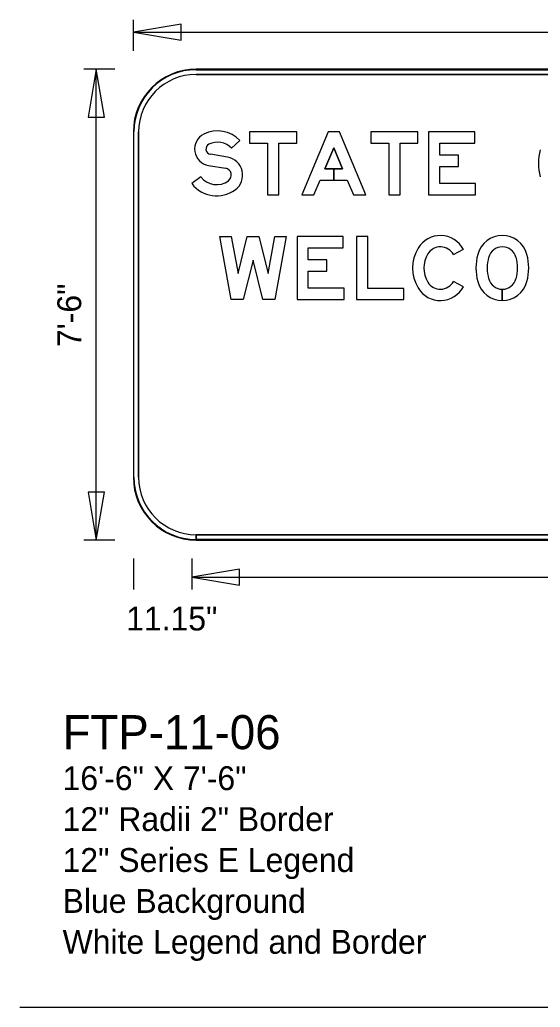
# Model space of a CAD drawing. Extents: x 0 to 770, y 0 to 495.
# Drawn here: x 0 to 76.3, y 330 to 474.8 of the extents above; entities that cross this region are included whole.
import ezdxf

# ---------------------------------------------------------------- set-up
doc = ezdxf.new("R2010")
doc.units = 0
for name, color, linetype in [('Default', 7, 'Continuous'), ('Dimension', 7, 'Continuous'), ('GSBWFill', 7, 'Continuous'), ('GSColorFill', 7, 'Continuous'), ('GSDims', 7, 'Continuous'), ('GSOutline', 7, 'Continuous'), ('SheetLines_dp', 7, 'Continuous')]:
    doc.layers.add(name, color=color, linetype=linetype)

msp = doc.modelspace()

# ---------------------------------------------------------------- linework, layer by layer
at = {"layer": 'Dimension'}
for points in [[(16.66, 473), (23.68, 471.81), (23.68, 474.19)], [(11.22, 467.56), (10.04, 460.55), (12.41, 460.55)], [(11.22, 398.51), (12.41, 405.53), (10.04, 405.53)], [(25.23, 393.07), (32.24, 391.88), (32.24, 394.26)]]:
    msp.add_lwpolyline(points, close=True, dxfattribs=at)
at = {"layer": 'GSBWFill'}
for p, q in [((159.37, 467.56), (25.87, 467.56)), ((159.37, 467.56), (25.87, 467.56)), ((25.87, 466.8), (159.37, 466.8)), ((16.66, 458.36), (16.66, 407.72)), ((16.66, 458.36), (16.66, 407.72)), ((17.43, 407.72), (17.43, 458.36)), ((31.05, 455.96), (32.27, 457.09)), ((30.46, 454.66), (27.95, 455.09)), ((27.67, 453.45), (30.18, 453.03)), ((26.54, 451.8), (25.23, 450.78)), ((63.58, 440.37), (65.05, 441.15)), ((65.05, 435.67), (63.58, 436.45)), ((63.58, 436.45), (63.58, 436.45)), ((70.75, 433.64), (70.75, 435.3)), ((70.75, 435.3), (70.75, 433.64)), ((25.87, 398.51), (25.87, 399.28)), ((25.87, 398.51), (159.37, 398.51)), ((159.37, 399.28), (25.88, 399.28)), ((25.88, 399.28), (25.88, 398.51)), ((25.88, 398.51), (159.37, 398.51))]:
    msp.add_line(p, q, dxfattribs=at)
for points in [[(33.7, 456.7), (36.32, 456.7), (36.32, 449.15), (37.98, 449.15), (37.98, 456.7), (40.6, 456.7), (40.6, 458.36), (33.7, 458.36)], [(47.33, 452.97), (46.03, 452.97), (46.03, 451.31), (48.02, 451.31), (48.93, 449.15), (50.73, 449.15), (46.86, 458.36), (45.2, 458.36), (41.34, 449.15), (43.14, 449.15), (44.04, 451.31), (46.03, 451.31), (46.03, 452.97), (44.74, 452.97), (46.03, 456.05)], [(51.47, 456.7), (54.09, 456.7), (54.09, 449.15), (55.75, 449.15), (55.75, 456.7), (58.37, 456.7), (58.37, 458.36), (51.47, 458.36)], [(66.84, 450.81), (61.59, 450.81), (61.59, 453.28), (64.31, 453.28), (64.31, 454.94), (61.59, 454.94), (61.59, 456.7), (66.7, 456.7), (66.7, 458.36), (59.94, 458.36), (59.94, 449.15), (66.84, 449.15)], [(34.2, 439.56), (32.75, 433.8), (31, 433.8), (29.32, 443.01), (31.01, 443.01), (32, 437.59), (33.36, 443.01), (35.04, 443.01), (36.41, 437.59), (37.4, 443.01), (39.08, 443.01), (37.4, 433.8), (35.65, 433.8)], [(47.55, 435.46), (42.3, 435.46), (42.3, 437.94), (45.02, 437.94), (45.02, 439.6), (42.3, 439.6), (42.3, 441.35), (47.41, 441.35), (47.41, 443.01), (40.65, 443.01), (40.65, 433.8), (47.55, 433.8)], [(56.3, 433.8), (56.3, 435.42), (51.05, 435.42), (51.05, 443.01), (49.39, 443.01), (49.39, 433.8)]]:
    msp.add_lwpolyline(points, close=True, dxfattribs=at)
for centre, radius, start, end in [((25.87, 458.36), 9.21, 90, 180), ((25.87, 458.36), 9.21, 90, 180), ((25.87, 458.36), 8.44, 90, 180), ((28.08, 455.86), 2.44, 116.9123, 260.4087), ((29, 454.05), 4.47, 42.8759, 116.9123), ((28.08, 455.86), 0.783, 116.9123, 260.4087), ((29, 454.05), 2.81, 42.8759, 116.9123), ((83.78, 453.75), 7.73, 165.0382, 194.9618), ((30.01, 452.03), 2.67, 306.123, 80.4087), ((30.01, 452.03), 1.01, 306.123, 80.4087), ((28.87, 453.59), 4.6, 217.5895, 306.123), ((28.87, 453.59), 2.95, 217.5895, 306.123), ((70.75, 439.44), 3.73, 14.9618, 165.0382), ((74.62, 438.41), 7.73, 165.0382, 194.9618), ((70.75, 439.44), 2.07, 14.9618, 165.0382), ((66.89, 438.41), 7.73, 345.0382, 14.9618), ((74.62, 438.41), 6.08, 165.0382, 194.9618), ((66.89, 438.41), 6.08, 345.0382, 14.9618), ((70.75, 437.37), 3.73, 194.9618, 270), ((70.75, 437.37), 2.07, 194.9618, 270), ((70.75, 437.37), 2.07, 270.0127, 345.0382), ((70.75, 437.37), 3.73, 270.0071, 345.0382), ((25.87, 407.72), 9.21, 180, 270), ((25.87, 407.72), 9.21, 180, 270), ((25.87, 407.72), 8.44, 180, 270)]:
    msp.add_arc(centre, radius, start, end, dxfattribs=at)
for centre, major_axis, start_param, end_param in [((61.67, 439.35), (0, 3.82), 5.201543, 7.308565), ((63.23, 438.41), (0, 5.64), 1.025379, 2.116213), ((63.23, 438.41), (0, 3.98), 1.025379, 2.116213), ((61.67, 439.35), (0, 2.16), 5.201543, 7.308565), ((61.67, 437.46), (0, 2.16), 2.116213, 4.223235), ((61.67, 437.46), (0, 3.82), 2.116213, 4.223235)]:
    msp.add_ellipse(centre, major_axis=major_axis, ratio=0.999994, start_param=start_param, end_param=end_param, dxfattribs=at)
at = {"layer": 'GSColorFill'}
for p, q in [((159.37, 467.56), (25.87, 467.56)), ((159.37, 467.56), (25.87, 467.56)), ((159.37, 467.56), (25.87, 467.56)), ((25.87, 467.49), (159.37, 467.49)), ((25.87, 466.8), (159.37, 466.8)), ((16.66, 458.36), (16.66, 407.72)), ((16.66, 458.36), (16.66, 407.72)), ((16.66, 458.36), (16.66, 407.72)), ((16.74, 407.72), (16.74, 458.36)), ((17.43, 407.72), (17.43, 458.36)), ((31.05, 455.96), (32.27, 457.09)), ((30.46, 454.66), (27.95, 455.09)), ((27.67, 453.45), (30.18, 453.03)), ((26.54, 451.8), (25.23, 450.78)), ((63.58, 440.37), (65.05, 441.15)), ((65.05, 435.67), (63.58, 436.45)), ((63.58, 436.45), (63.58, 436.45)), ((70.75, 433.64), (70.75, 435.3)), ((70.75, 435.3), (70.75, 433.64)), ((25.87, 398.51), (25.87, 399.28)), ((25.87, 398.51), (25.87, 398.59)), ((159.37, 398.59), (25.87, 398.59)), ((25.87, 398.59), (25.87, 398.51)), ((25.87, 398.51), (159.37, 398.51)), ((25.87, 398.51), (159.37, 398.51)), ((159.37, 399.28), (25.88, 399.28)), ((25.88, 399.28), (25.88, 398.51)), ((25.88, 398.51), (159.37, 398.51))]:
    msp.add_line(p, q, dxfattribs=at)
for points in [[(33.7, 456.7), (36.32, 456.7), (36.32, 449.15), (37.98, 449.15), (37.98, 456.7), (40.6, 456.7), (40.6, 458.36), (33.7, 458.36)], [(47.33, 452.97), (46.03, 452.97), (46.03, 451.31), (48.02, 451.31), (48.93, 449.15), (50.73, 449.15), (46.86, 458.36), (45.2, 458.36), (41.34, 449.15), (43.14, 449.15), (44.04, 451.31), (46.03, 451.31), (46.03, 452.97), (44.74, 452.97), (46.03, 456.05)], [(51.47, 456.7), (54.09, 456.7), (54.09, 449.15), (55.75, 449.15), (55.75, 456.7), (58.37, 456.7), (58.37, 458.36), (51.47, 458.36)], [(66.84, 450.81), (61.59, 450.81), (61.59, 453.28), (64.31, 453.28), (64.31, 454.94), (61.59, 454.94), (61.59, 456.7), (66.7, 456.7), (66.7, 458.36), (59.94, 458.36), (59.94, 449.15), (66.84, 449.15)], [(34.2, 439.56), (32.75, 433.8), (31, 433.8), (29.32, 443.01), (31.01, 443.01), (32, 437.59), (33.36, 443.01), (35.04, 443.01), (36.41, 437.59), (37.4, 443.01), (39.08, 443.01), (37.4, 433.8), (35.65, 433.8)], [(47.55, 435.46), (42.3, 435.46), (42.3, 437.94), (45.02, 437.94), (45.02, 439.6), (42.3, 439.6), (42.3, 441.35), (47.41, 441.35), (47.41, 443.01), (40.65, 443.01), (40.65, 433.8), (47.55, 433.8)], [(56.3, 433.8), (56.3, 435.42), (51.05, 435.42), (51.05, 443.01), (49.39, 443.01), (49.39, 433.8)]]:
    msp.add_lwpolyline(points, close=True, dxfattribs=at)
for centre, radius, start, end in [((25.87, 458.36), 9.21, 90, 180), ((25.87, 458.36), 9.21, 90, 180), ((25.87, 458.36), 9.21, 90, 180), ((25.87, 458.36), 9.13, 90, 180), ((25.87, 458.36), 8.44, 90, 180), ((28.08, 455.86), 2.44, 116.9123, 260.4087), ((29, 454.05), 4.47, 42.8759, 116.9123), ((28.08, 455.86), 0.783, 116.9123, 260.4087), ((29, 454.05), 2.81, 42.8759, 116.9123), ((83.78, 453.75), 7.73, 165.0382, 194.9618), ((30.01, 452.03), 2.67, 306.123, 80.4087), ((30.01, 452.03), 1.01, 306.123, 80.4087), ((28.87, 453.59), 4.6, 217.5895, 306.123), ((28.87, 453.59), 2.95, 217.5895, 306.123), ((70.75, 439.44), 3.73, 14.9618, 165.0382), ((74.62, 438.41), 7.73, 165.0382, 194.9618), ((70.75, 439.44), 2.07, 14.9618, 165.0382), ((66.89, 438.41), 7.73, 345.0382, 14.9618), ((74.62, 438.41), 6.08, 165.0382, 194.9618), ((66.89, 438.41), 6.08, 345.0382, 14.9618), ((70.75, 437.37), 3.73, 194.9618, 270), ((70.75, 437.37), 2.07, 194.9618, 270), ((70.75, 437.37), 2.07, 270.0127, 345.0382), ((70.75, 437.37), 3.73, 270.0071, 345.0382), ((25.87, 407.72), 9.21, 180, 270), ((25.87, 407.72), 9.21, 180, 270), ((25.87, 407.72), 9.21, 180, 270), ((25.87, 407.72), 9.13, 180, 270), ((25.87, 407.72), 8.44, 180, 270)]:
    msp.add_arc(centre, radius, start, end, dxfattribs=at)
for centre, major_axis, start_param, end_param in [((61.67, 439.35), (0, 3.82), 5.201543, 7.308565), ((63.23, 438.41), (0, 5.64), 1.025379, 2.116213), ((63.23, 438.41), (0, 3.98), 1.025379, 2.116213), ((61.67, 439.35), (0, 2.16), 5.201543, 7.308565), ((61.67, 437.46), (0, 2.16), 2.116213, 4.223235), ((61.67, 437.46), (0, 3.82), 2.116213, 4.223235)]:
    msp.add_ellipse(centre, major_axis=major_axis, ratio=0.999994, start_param=start_param, end_param=end_param, dxfattribs=at)
at = {"layer": 'GSDims'}
for p, q in [((16.66, 470.28), (16.66, 474.81)), ((16.66, 473), (168.58, 473)), ((13.94, 467.56), (9.41, 467.56)), ((11.22, 398.51), (11.22, 467.56)), ((13.94, 398.51), (9.41, 398.51)), ((16.66, 395.79), (16.66, 391.26)), ((25.23, 395.79), (25.23, 391.26)), ((25.23, 395.79), (25.23, 391.26)), ((25.23, 393.07), (160.02, 393.07))]:
    msp.add_line(p, q, dxfattribs=at)
at = {"layer": 'GSOutline'}
for p, q in [((159.37, 467.56), (25.87, 467.56)), ((159.37, 467.56), (25.87, 467.56)), ((159.37, 466.8), (25.87, 466.8)), ((16.66, 458.36), (16.66, 407.72)), ((16.66, 458.36), (16.66, 407.72)), ((17.43, 458.36), (17.43, 407.72)), ((31.05, 455.96), (32.27, 457.09)), ((30.46, 454.66), (27.95, 455.09)), ((27.67, 453.45), (30.18, 453.03)), ((26.54, 451.8), (25.23, 450.78)), ((63.58, 440.37), (65.05, 441.15)), ((65.05, 435.67), (63.58, 436.45)), ((63.58, 436.45), (63.58, 436.45)), ((25.87, 399.28), (159.37, 399.28)), ((25.87, 398.51), (159.37, 398.51)), ((25.87, 398.51), (159.37, 398.51))]:
    msp.add_line(p, q, dxfattribs=at)
for points in [[(33.7, 456.7), (36.32, 456.7), (36.32, 449.15), (37.98, 449.15), (37.98, 456.7), (40.6, 456.7), (40.6, 458.36), (33.7, 458.36)], [(44.04, 451.31), (48.02, 451.31), (48.93, 449.15), (50.73, 449.15), (46.86, 458.36), (45.2, 458.36), (41.34, 449.15), (43.14, 449.15)], [(51.47, 456.7), (54.09, 456.7), (54.09, 449.15), (55.75, 449.15), (55.75, 456.7), (58.37, 456.7), (58.37, 458.36), (51.47, 458.36)], [(66.84, 450.81), (61.59, 450.81), (61.59, 453.28), (64.31, 453.28), (64.31, 454.94), (61.59, 454.94), (61.59, 456.7), (66.7, 456.7), (66.7, 458.36), (59.94, 458.36), (59.94, 449.15), (66.84, 449.15)], [(47.33, 452.97), (46.03, 456.05), (44.74, 452.97)], [(34.2, 439.56), (32.75, 433.8), (31, 433.8), (29.32, 443.01), (31.01, 443.01), (32, 437.59), (33.36, 443.01), (35.04, 443.01), (36.41, 437.59), (37.4, 443.01), (39.08, 443.01), (37.4, 433.8), (35.65, 433.8)], [(47.55, 435.46), (42.3, 435.46), (42.3, 437.94), (45.02, 437.94), (45.02, 439.6), (42.3, 439.6), (42.3, 441.35), (47.41, 441.35), (47.41, 443.01), (40.65, 443.01), (40.65, 433.8), (47.55, 433.8)], [(56.3, 433.8), (56.3, 435.42), (51.05, 435.42), (51.05, 443.01), (49.39, 443.01), (49.39, 433.8)]]:
    msp.add_lwpolyline(points, close=True, dxfattribs=at)
for centre, radius, start, end in [((25.87, 458.36), 9.21, 90, 180), ((25.87, 458.36), 9.21, 90, 180), ((25.87, 458.36), 8.44, 90, 180), ((28.08, 455.86), 2.44, 116.9123, 260.4087), ((29, 454.05), 4.47, 42.8759, 116.9123), ((28.08, 455.86), 0.783, 116.9123, 260.4087), ((29, 454.05), 2.81, 42.8759, 116.9123), ((83.78, 453.75), 7.73, 165.0382, 194.9618), ((30.01, 452.03), 2.67, 306.123, 80.4087), ((30.01, 452.03), 1.01, 306.123, 80.4087), ((28.87, 453.59), 4.6, 217.5895, 306.123), ((28.87, 453.59), 2.95, 217.5895, 306.123), ((70.75, 439.44), 3.73, 14.9618, 165.0382), ((74.62, 438.41), 7.73, 165.0382, 194.9618), ((70.75, 439.44), 2.07, 14.9618, 165.0382), ((66.89, 438.41), 7.73, 345.0382, 14.9618), ((74.62, 438.41), 6.08, 165.0382, 194.9618), ((66.89, 438.41), 6.08, 345.0382, 14.9618), ((70.75, 437.37), 3.73, 194.9618, 345.0382), ((70.75, 437.37), 2.07, 194.9618, 345.0382), ((25.87, 407.72), 9.21, 180, 270), ((25.87, 407.72), 9.21, 180, 270), ((25.87, 407.72), 8.44, 180, 270)]:
    msp.add_arc(centre, radius, start, end, dxfattribs=at)
for centre, major_axis, start_param, end_param in [((61.67, 439.35), (0, 3.82), 5.201543, 7.308565), ((63.23, 438.41), (0, 5.64), 1.025379, 2.116213), ((63.23, 438.41), (0, 3.98), 1.025379, 2.116213), ((61.67, 439.35), (0, 2.16), 5.201543, 7.308565), ((61.67, 437.46), (0, 2.16), 2.116213, 4.223235), ((61.67, 437.46), (0, 3.82), 2.116213, 4.223235)]:
    msp.add_ellipse(centre, major_axis=major_axis, ratio=0.999994, start_param=start_param, end_param=end_param, dxfattribs=at)
at = {"layer": 'SheetLines_dp'}
msp.add_line((0, 330), (770, 330), dxfattribs=at)

# ---------------------------------------------------------------- texts
at = {"layer": 'Default'}
msp.add_text('7\'-6"', height=3.5, rotation=90, dxfattribs=at).set_placement((9.01, 426.81))
for s, height, p in [('11.15"', 3.5, (15.6, 385.25)), ('FTP-11-06', 5, (6.28, 367.84)), ('16\'-6" X 7\'-6" ', 3.5, (6.28, 361.84)), ('12" Radii 2" Border', 3.5, (6.28, 355.84)), ('12" Series E Legend', 3.5, (6.28, 349.84)), ('Blue Background', 3.5, (6.28, 343.84)), ('White Legend and Border', 3.5, (6.28, 337.84))]:
    msp.add_text(s, height=height, dxfattribs=at).set_placement(p)

doc.saveas('drawing.dxf')
